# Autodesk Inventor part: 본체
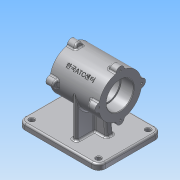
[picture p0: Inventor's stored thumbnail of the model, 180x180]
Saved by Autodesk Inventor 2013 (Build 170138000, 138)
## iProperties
Created: 2015-12
Part Number: 본체
Material: 알루미늄 6061
Document SubType Name: Modeling
Designer: Administrator
Density: 2.71 g/cm^3
Mass: 1165.02 g
Surface Area: 814.938 cm^2
Volume: 429.895 cm^3
Author: Administrator
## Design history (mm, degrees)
sketch "스케치1"
  geometry: L1 (-68, 55)-(48, 55); L2 (60, 43)-(60, -43); L3 (48, -55)-(-68, -55); L4 (-80, -43)-(-80, 43); C1 r 4 at (-68, 43); C2 r 4 at (-68, -43); C3 r 4 at (48, -43); C4 r 4 at (48, 43); A1 r 12 centre (-68, 43) between (-68, 55) and (-80, 43); A2 r 12 centre (-68, -43) between (-80, -43) and (-68, -55); A3 r 12 centre (48, -43) between (48, -55) and (60, -43); A4 r 12 centre (48, 43) between (60, 43) and (48, 55); 5 further points
  constraints: 8 centre point, 8 end point, 8 point on circle, 8 tangent, 6 equal radius, 6 point on line, 4 coincident, 2 parallel, 1 horizontal, 1 horizontal alignment, 1 midpoint, 1 perpendicular
  dimensions: "d0" = 110 distance of point (60, 55) point (60, -55); "d2" = 140 distance of point (-80, 55) point (60, 55); "d3" = 80 distance from line of point (0, 0) L4; "d4" = 12 radius of A1; "d5" = 8 diameter of C1
extrude "돌출1" new body sketch "스케치1" distance "d6" = 10; taper "d7" = 0 deg
chamfer "모따기1" distance "d8" = 1; stored, may be unused: second distance "d9" = 2, angle "d10" = 45 deg
chamfer "모따기2" distance "d11" = 1; stored, may be unused: second distance "d12" = 2, angle "d13" = 45 deg
chamfer "모따기3" distance "d14" = 1; stored, may be unused: second distance "d15" = 2, angle "d16" = 45 deg
chamfer "모따기4" distance "d17" = 1; stored, may be unused: second distance "d18" = 2, angle "d19" = 45 deg
sketch "스케치2"
  geometry: L1 (43, 0)-(-43, 0) reference; C1 r 37 at (0, 80); 2 further points
  constraints: 1 centre point, 1 midpoint, 1 vertical alignment
  dimensions: "d20" = 80 distance from line of L1 C1.centre; "d21" = 74 diameter of C1
extrude "돌출2" join sketch "스케치2" stored distance "d22" = 85; taper "d23" = 0 deg
fillet "모깎기1" dims "d29" = 3
sketch "스케치4"
  geometry: L1 (4, -37)-(-4, -37); L2 (-4, -37)-(-4, 37); L3 (-4, 37)-(4, 37); L4 (4, 37)-(4, -37); 3 further points
  constraints: 8 end point, 2 midpoint, 2 parallel, 1 horizontal, 1 horizontal alignment, 1 perpendicular, 1 vertical alignment
  dimensions: "d32" = 8 distance of L2.end L3.end; "d34" = 74 distance of L3.end L1.start
extrude "돌출4" join sketch "스케치4" stored distance "d35" = 15; taper "d36" = 0 deg
sketch "스케치5"
  geometry: L1 (42.5, 43)-(-42.5, 43) reference; L2 (-48, 10)-(68, 10) reference; L3 (-25, 10)-(-19.475, 55); L4 (-19.475, 55)-(19.475, 55); L5 (19.475, 55)-(25, 10); L6 (-25, 10)-(25, 10); 2 further points
  constraints: 8 end point, 2 point on line, 1 collinear, 1 equal length, 1 midpoint, 1 parallel, 1 vertical alignment
  dimensions: "d37" = 97 deg angle of L2 L3; "d38" = 50 distance of L3.start L5.end; "d40" = 45 distance between parallel lines of L2 L4
extrude "돌출5" join sketch "스케치5" stored distance "d41" = 12; taper "d42" = 0 deg
fillet "모깎기2" dims "d43" = 3
fillet "모깎기3" dims "d44" = 3
fillet "모깎기4" dims "d45" = 3
fillet "모깎기5" dims "d46" = 3
fillet "모깎기6" dims "d47" = 3
hole "구멍1" diameter "d50" = 42; stored, may be unused: countersink angle "d54" = 90 deg, drill point angle "d56" = 118 deg; dims "d51" = 6, "d52" = 47, "d53" = 22, "d55" = 8, "d66" = 10, "d67" = 10
hole "구멍2" diameter "d59" = 47; stored, may be unused: countersink angle "d63" = 90 deg, drill point angle "d65" = 0 deg; dims "d57" = 10, "d58" = 10, "d60" = 6, "d61" = 47, "d62" = 22, "d64" = 22
chamfer "모따기5" distance "d68" = 1; stored, may be unused: second distance "d69" = 2, angle "d70" = 45 deg
chamfer "모따기6" distance "d71" = 1; stored, may be unused: second distance "d72" = 2, angle "d73" = 45 deg
fillet "모깎기7" dims "d74" = 0.3
node "작업 평면3"
  node "작업 평면2"
sketch "스케치6"
  geometry: L1 (-24.887, 2.435)-(24.887, 2.435); L2 (24.887, 2.435)-(24.887, -2.435); L3 (24.887, -2.435)-(-24.887, -2.435); L4 (-24.887, -2.435)-(-24.887, 2.435); L5 (-42.5, 37)-(-42.5, -37) reference; 5 further points
  constraints: 3 midpoint, 2 horizontal alignment, 2 vertical alignment, 1 horizontal, 2 other
  dimensions: "d77" = 67.38738 distance between parallel lines of L2 L5; "d78" = 4.86969 distance between parallel lines of L1 L3
feature "엠보싱1" sketch "스케치6" dims "d8" = 1, "d79" = 0.5, "d80" = 0
sketch "스케치8"
  geometry: C1 r 24.5 at (0, 0) reference; A1 r 37 centre (0, 0) between (-37, 0) and (-36.338, -6.969) reference; A2 r 7 centre (-37, 0) between (-36.338, 6.969) and (-36.338, -6.969); 1 further point
  constraints: 5 point on circle, 1 centre point, 1 horizontal alignment
  dimensions: "d95" = 14 diameter of A2
extrude "돌출7" new body sketch "스케치8" distance "d97" = 15; taper "d98" = 0 deg
node "작업 평면10"
  node "작업축8"
feature "분할2"
feature "분할3"
feature "분할4"
feature "분할5"
feature "결합1"
  node "솔리드4"
fillet "모깎기8" dims "d106" = 3
fillet "모깎기9" dims "d107" = 3
hole "구멍3" diameter "d110" = 3.242; stored, may be unused: countersink angle "d114" = 90 deg, drill point angle "d116" = 118 deg; dims "d108" = 10, "d109" = 10, "d111" = 9, "d112" = 47, "d113" = 22, "d115" = 11
hole "구멍4" diameter "d119" = 3.242; stored, may be unused: countersink angle "d123" = 90 deg, drill point angle "d125" = 118 deg; dims "d117" = 10, "d118" = 10, "d120" = 9, "d121" = 47, "d122" = 22, "d124" = 11
hole "구멍5" diameter "d128" = 3.242; stored, may be unused: countersink angle "d132" = 90 deg, drill point angle "d134" = 118 deg; dims "d126" = 10, "d127" = 10, "d129" = 9, "d130" = 47, "d131" = 22, "d133" = 11
hole "구멍6" diameter "d137" = 3.242; stored, may be unused: countersink angle "d141" = 90 deg, drill point angle "d143" = 118 deg; dims "d135" = 10, "d136" = 10, "d138" = 9, "d139" = 47, "d140" = 22, "d142" = 11
node "솔리드1"
pattern_circular "원형 패턴2" dims angle "d104" = 360 deg
mirror "대칭2"
mirror "대칭3"
node "작업축2"
node "투영된 루프2"
node "작업 평면11"
node "작업 평면12"
node "작업 평면13"
other parameters: "d76" = 135 deg, "d99" = -20 deg
